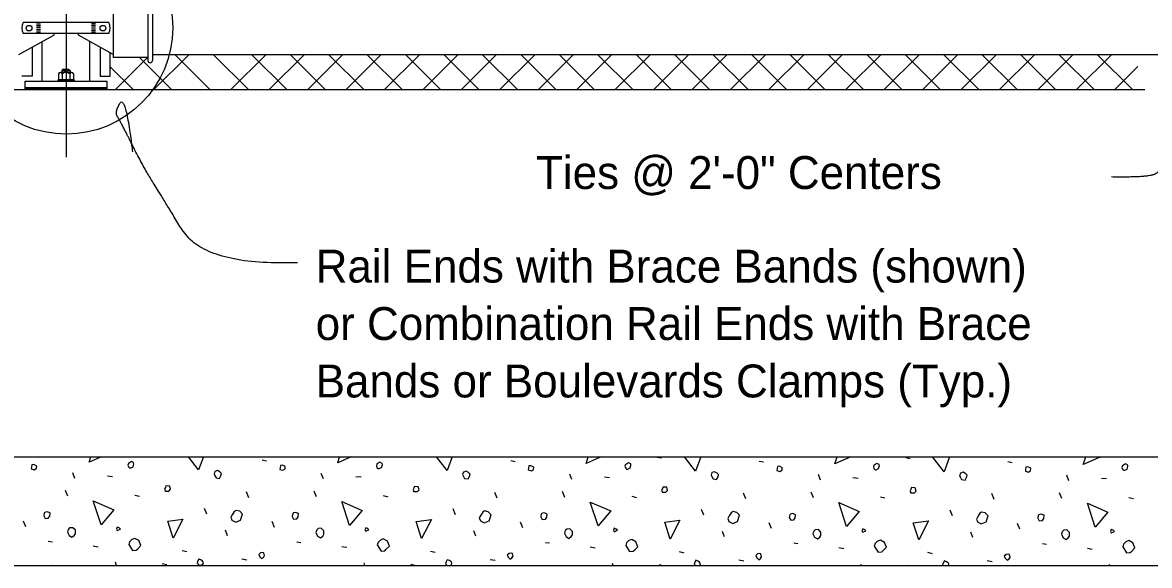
# Model space of a CAD drawing. Extents: x 0 to 41.1, y 0 to 25.9.
# Drawn here: x 11.81 to 18.72, y 14.04 to 17.37 of the extents above; entities that cross this region are included whole.
import ezdxf

# ---------------------------------------------------------------- set-up
doc = ezdxf.new("R2010")
doc.units = 0
for name, color, linetype in [('CL_Major', 7, 'Continuous'), ('Dimension', 7, 'Continuous'), ('Miscellaneous', 7, 'Continuous'), ('SteelMisc', 7, 'Continuous'), ('SupstrConc', 7, 'Continuous'), ('TextStructures', 7, 'Continuous')]:
    doc.layers.add(name, color=color, linetype=linetype)

msp = doc.modelspace()

# ---------------------------------------------------------------- linework, layer by layer
at = {"layer": 'CL_Major'}
msp.add_line((12.075, 24.4537), (12.075, 16.5436), dxfattribs=at)
at = {"layer": 'Dimension'}
msp.add_line((12.075, 17.0171), (12.075, 17.0164), dxfattribs=at)
msp.add_circle((12.0765, 17.337), 0.6527, dxfattribs=at)
for points in [[(18.4847, 16.4238), (18.7076, 16.4203), (18.7925, 16.4592), (18.9233, 16.6079), (18.8385, 16.9053), (18.796, 17.1707)], [(13.4943, 15.8955), (12.9219, 15.8776), (12.6525, 16.3184), (12.5475, 16.4863), (12.4086, 16.7637), (12.3723, 16.8197), (12.4405, 16.93), (12.4826, 16.5757)]]:
    msp.add_open_spline(points, degree=2, dxfattribs=at)
at = {"layer": 'Miscellaneous'}
for p, q in [((12.3786, 16.9573), (12.5775, 17.1562)), ((12.5254, 17.1536), (12.7217, 16.9573)), ((12.6143, 16.9573), (12.8278, 17.1708)), ((12.7439, 17.1708), (12.9574, 16.9573)), ((12.9796, 17.1708), (13.1931, 16.9573)), ((13.0857, 16.9573), (13.2992, 17.1708)), ((13.2153, 17.1708), (13.4288, 16.9573)), ((13.3214, 16.9573), (13.5349, 17.1708)), ((13.451, 17.1708), (13.6645, 16.9573)), ((13.5571, 16.9573), (13.7706, 17.1708)), ((13.6867, 17.1708), (13.9002, 16.9573)), ((13.7928, 16.9573), (14.0063, 17.1708)), ((13.9224, 17.1708), (14.1359, 16.9573)), ((14.0285, 16.9573), (14.242, 17.1708)), ((14.1581, 17.1708), (14.3716, 16.9573)), ((14.2642, 16.9573), (14.4777, 17.1708)), ((14.3938, 17.1708), (14.6073, 16.9573)), ((14.4999, 16.9573), (14.7134, 17.1708)), ((14.6295, 17.1708), (14.843, 16.9573)), ((14.7356, 16.9573), (14.9491, 17.1708)), ((14.8652, 17.1708), (15.0787, 16.9573)), ((14.9713, 16.9573), (15.1848, 17.1708)), ((15.1009, 17.1708), (15.3144, 16.9573)), ((15.207, 16.9573), (15.4205, 17.1708)), ((15.3366, 17.1708), (15.5501, 16.9573)), ((15.4427, 16.9573), (15.6562, 17.1708)), ((15.5723, 17.1708), (15.7858, 16.9573)), ((15.6784, 16.9573), (15.8919, 17.1708)), ((15.808, 17.1708), (16.0215, 16.9573)), ((15.9141, 16.9573), (16.1276, 17.1708)), ((16.0437, 17.1708), (16.2573, 16.9573)), ((16.1498, 16.9573), (16.3633, 17.1708)), ((16.2794, 17.1708), (16.493, 16.9573)), ((16.3855, 16.9573), (16.599, 17.1708)), ((16.5151, 17.1708), (16.7287, 16.9573)), ((16.6212, 16.9573), (16.8347, 17.1708)), ((16.7508, 17.1708), (16.9644, 16.9573)), ((16.8569, 16.9573), (17.0704, 17.1708)), ((16.9865, 17.1708), (17.2001, 16.9573)), ((17.0926, 16.9573), (17.3061, 17.1708)), ((17.2222, 17.1708), (17.4358, 16.9573)), ((17.3283, 16.9573), (17.5418, 17.1708)), ((17.4579, 17.1708), (17.6715, 16.9573)), ((17.564, 16.9573), (17.7776, 17.1708)), ((17.6936, 17.1708), (17.9072, 16.9573)), ((17.7997, 16.9573), (18.0133, 17.1708)), ((17.9293, 17.1708), (18.1429, 16.9573)), ((18.0354, 16.9573), (18.249, 17.1708)), ((18.165, 17.1708), (18.3786, 16.9573)), ((18.2711, 16.9573), (18.4847, 17.1708)), ((18.4007, 17.1708), (18.6143, 16.9573)), ((12.0638, 17.0788), (12.0846, 17.0788)), ((12.0638, 17.0691), (12.0846, 17.0691)), ((12.3459, 17.0974), (12.486, 16.9573)), ((18.5068, 16.9573), (18.6477, 17.0982)), ((11.825, 16.9642), (12.325, 16.9642)), ((11.825, 16.9607), (12.325, 16.9607)), ((12.6778, 14.7072), (12.6789, 14.707)), ((13.2781, 14.6876), (13.3046, 14.6823)), ((14.1839, 14.7072), (14.2027, 14.7035)), ((14.8019, 14.684), (14.8285, 14.6787)), ((15.7, 14.7053), (15.7265, 14.7)), ((16.3258, 14.6805), (16.3523, 14.6752)), ((17.2238, 14.7017), (17.2503, 14.6964)), ((17.8496, 14.677), (17.8761, 14.6717)), ((12.1291, 14.5744), (12.1167, 14.608)), ((12.3288, 14.5904), (12.3607, 14.5868)), ((13.6529, 14.5709), (13.6405, 14.6045)), ((13.8527, 14.5868), (13.8845, 14.5833)), ((15.1767, 14.5674), (15.1643, 14.601)), ((15.3765, 14.5833), (15.4083, 14.5797)), ((16.7005, 14.5638), (16.6882, 14.5974)), ((18.2243, 14.5603), (18.212, 14.5939)), ((16.9003, 14.5797), (16.9321, 14.5762)), ((18.4241, 14.5762), (18.4559, 14.5727)), ((12.0867, 14.4648), (12.0725, 14.5002)), ((12.4968, 14.4719), (12.5251, 14.4648)), ((13.195, 14.456), (13.1809, 14.4914)), ((13.6105, 14.4613), (13.5963, 14.4967)), ((14.0206, 14.4684), (14.0489, 14.4613)), ((14.7189, 14.4525), (14.7047, 14.4878)), ((15.1343, 14.4578), (15.1201, 14.4931)), ((15.5444, 14.4648), (15.5727, 14.4578)), ((16.2427, 14.4489), (16.2285, 14.4843)), ((16.6581, 14.4542), (16.644, 14.4896)), ((17.0682, 14.4613), (17.0965, 14.4542)), ((17.7665, 14.4454), (17.7523, 14.4807)), ((18.1819, 14.4507), (18.1678, 14.4861)), ((18.592, 14.4578), (18.6203, 14.4507)), ((12.9387, 14.3552), (12.9246, 14.3906)), ((14.4625, 14.3517), (14.4484, 14.3871)), ((15.9863, 14.3482), (15.9722, 14.3835)), ((17.5102, 14.3446), (17.496, 14.38)), ((11.8286, 14.2775), (11.8144, 14.3128)), ((13.3524, 14.2739), (13.3382, 14.3093)), ((14.8762, 14.2704), (14.8621, 14.3057)), ((13.0642, 14.2227), (13.0519, 14.2562)), ((14.588, 14.2191), (14.5757, 14.2527)), ((16.1119, 14.2156), (16.0995, 14.2492)), ((16.4, 14.2668), (16.3859, 14.3022)), ((17.6357, 14.212), (17.6233, 14.2456)), ((17.9238, 14.2633), (17.9097, 14.2987)), ((11.9664, 14.1891), (11.9912, 14.1855)), ((13.4903, 14.1855), (13.515, 14.182)), ((15.0141, 14.182), (15.0388, 14.1785)), ((16.5379, 14.1785), (16.5626, 14.1749)), ((18.0617, 14.1749), (18.0865, 14.1714)), ((12.2422, 14.1608), (12.2723, 14.1555)), ((12.7867, 14.1325), (12.815, 14.1254)), ((13.766, 14.1572), (13.7961, 14.1519)), ((14.3105, 14.129), (14.3388, 14.1219)), ((15.2898, 14.1537), (15.3199, 14.1484)), ((15.8343, 14.1254), (15.8626, 14.1184)), ((16.8137, 14.1502), (16.8437, 14.1449)), ((17.3581, 14.1219), (17.3864, 14.1148)), ((18.3375, 14.1466), (18.3675, 14.1413)), ((12.3855, 14.0406), (12.3783, 14.06)), ((12.6647, 14.0529), (12.693, 14.0459)), ((13.1526, 14.0812), (13.1827, 14.0759)), ((13.908, 14.0406), (13.9022, 14.0565)), ((14.1885, 14.0494), (14.2168, 14.0423)), ((14.6764, 14.0777), (14.7065, 14.0724)), ((15.4305, 14.0406), (15.426, 14.0529)), ((15.7123, 14.0459), (15.7336, 14.0406)), ((16.2002, 14.0742), (16.2303, 14.0689)), ((16.953, 14.0406), (16.9498, 14.0494)), ((17.2362, 14.0423), (17.2432, 14.0406)), ((17.7241, 14.0706), (17.7541, 14.0653)), ((18.4756, 14.0406), (18.4736, 14.0459))]:
    msp.add_line(p, q, dxfattribs=at)
msp.add_lwpolyline([(11.825, 16.9677), (12.325, 16.9677), (12.325, 16.9573), (11.825, 16.9573)], close=True, dxfattribs=at)
for points in [[(11.8621, 14.6328), (11.8816, 14.6275), (11.894, 14.6363), (11.8957, 14.6487), (11.8922, 14.6522), (11.8781, 14.6593), (11.8657, 14.6575), (11.8639, 14.6452), (11.8621, 14.6328)], [(12.2175, 14.6734), (12.2279, 14.7072)], [(12.2927, 14.7072), (12.2175, 14.6734)], [(12.465, 14.6381), (12.472, 14.6381), (12.4862, 14.6452), (12.4915, 14.6611), (12.4897, 14.6699), (12.4756, 14.677), (12.4579, 14.6664), (12.4544, 14.6558), (12.4579, 14.6452), (12.465, 14.6381)], [(12.8875, 14.6257), (12.8255, 14.7072)], [(12.9179, 14.7072), (12.8875, 14.6257)], [(13.386, 14.6292), (13.4054, 14.6239), (13.4178, 14.6328), (13.4196, 14.6452), (13.416, 14.6487), (13.4019, 14.6558), (13.3895, 14.654), (13.3877, 14.6416), (13.386, 14.6292)], [(13.7413, 14.6699), (13.7528, 14.7072)], [(13.8244, 14.7072), (13.7413, 14.6699)], [(13.9888, 14.6345), (13.9958, 14.6345), (14.01, 14.6416), (14.0153, 14.6575), (14.0135, 14.6664), (13.9994, 14.6734), (13.9817, 14.6628), (13.9782, 14.6522), (13.9817, 14.6416), (13.9888, 14.6345)], [(14.4113, 14.6222), (14.3466, 14.7072)], [(14.4431, 14.7072), (14.4113, 14.6222)], [(14.9098, 14.6257), (14.9292, 14.6204), (14.9416, 14.6292), (14.9434, 14.6416), (14.9398, 14.6452), (14.9257, 14.6522), (14.9133, 14.6505), (14.9115, 14.6381), (14.9098, 14.6257)], [(15.2651, 14.6664), (15.2777, 14.7072)], [(15.3561, 14.7072), (15.2651, 14.6664)], [(15.5126, 14.631), (15.5197, 14.631), (15.5338, 14.6381), (15.5391, 14.654), (15.5373, 14.6628), (15.5232, 14.6699), (15.5055, 14.6593), (15.502, 14.6487), (15.5055, 14.6381), (15.5126, 14.631)], [(15.9351, 14.6186), (15.8677, 14.7072)], [(15.9682, 14.7072), (15.9351, 14.6186)], [(16.7889, 14.6628), (16.8026, 14.7072)], [(16.8878, 14.7072), (16.7889, 14.6628)], [(17.0364, 14.6275), (17.0435, 14.6275), (17.0576, 14.6345), (17.0629, 14.6505), (17.0612, 14.6593), (17.047, 14.6664), (17.0293, 14.6558), (17.0258, 14.6452), (17.0293, 14.6345), (17.0364, 14.6275)], [(17.4589, 14.6151), (17.3889, 14.7072)], [(17.4933, 14.7072), (17.4589, 14.6151)], [(18.3127, 14.6593), (18.3275, 14.7072)], [(18.4195, 14.7072), (18.3127, 14.6593)], [(18.5602, 14.6239), (18.5673, 14.6239), (18.5814, 14.631), (18.5867, 14.6469), (18.585, 14.6558), (18.5708, 14.6628), (18.5531, 14.6522), (18.5496, 14.6416), (18.5531, 14.631), (18.5602, 14.6239)], [(12.9864, 14.5939), (12.9953, 14.578), (13.0165, 14.5744), (13.0253, 14.5904), (13.0289, 14.6045), (13.02, 14.6133), (13.0041, 14.6222), (12.9882, 14.6169), (12.9829, 14.601), (12.9864, 14.5939)], [(14.5103, 14.5904), (14.5191, 14.5744), (14.5403, 14.5709), (14.5492, 14.5868), (14.5527, 14.601), (14.5439, 14.6098), (14.5279, 14.6186), (14.512, 14.6133), (14.5067, 14.5974), (14.5103, 14.5904)], [(16.0341, 14.5868), (16.0429, 14.5709), (16.0641, 14.5674), (16.073, 14.5833), (16.0765, 14.5974), (16.0677, 14.6063), (16.0518, 14.6151), (16.0358, 14.6098), (16.0305, 14.5939), (16.0341, 14.5868)], [(16.4336, 14.6222), (16.453, 14.6169), (16.4654, 14.6257), (16.4672, 14.6381), (16.4636, 14.6416), (16.4495, 14.6487), (16.4371, 14.6469), (16.4354, 14.6345), (16.4336, 14.6222)], [(17.5579, 14.5833), (17.5667, 14.5674), (17.5879, 14.5638), (17.5968, 14.5797), (17.6003, 14.5939), (17.5915, 14.6027), (17.5756, 14.6116), (17.5597, 14.6063), (17.5544, 14.5904), (17.5579, 14.5833)], [(17.9574, 14.6186), (17.9769, 14.6133), (17.9892, 14.6222), (17.991, 14.6345), (17.9875, 14.6381), (17.9733, 14.6452), (17.9609, 14.6434), (17.9592, 14.631), (17.9574, 14.6186)], [(12.6842, 14.4967), (12.7054, 14.4967), (12.716, 14.5073), (12.7107, 14.5267), (12.6877, 14.5285), (12.6842, 14.5179), (12.6789, 14.509), (12.6842, 14.4967), (12.6806, 14.5002)], [(14.208, 14.4931), (14.2292, 14.4931), (14.2398, 14.5037), (14.2345, 14.5232), (14.2115, 14.5249), (14.208, 14.5143), (14.2027, 14.5055), (14.208, 14.4931), (14.2044, 14.4967)], [(15.7318, 14.4896), (15.753, 14.4896), (15.7636, 14.5002), (15.7583, 14.5196), (15.7353, 14.5214), (15.7318, 14.5108), (15.7265, 14.502), (15.7318, 14.4896), (15.7283, 14.4931)], [(17.2556, 14.4861), (17.2768, 14.4861), (17.2874, 14.4967), (17.2821, 14.5161), (17.2591, 14.5179), (17.2556, 14.5073), (17.2503, 14.4984), (17.2556, 14.4861), (17.2521, 14.4896)], [(12.2899, 14.2898), (12.2422, 14.4366), (12.3677, 14.3818), (12.2899, 14.2898)], [(13.0925, 14.3181), (13.1155, 14.3057), (13.1455, 14.3181), (13.1579, 14.3552), (13.1402, 14.3729), (13.1173, 14.3782), (13.1067, 14.3711), (13.0943, 14.3517), (13.0854, 14.3358), (13.0925, 14.3181)], [(13.8138, 14.2863), (13.766, 14.433), (13.8915, 14.3782), (13.8138, 14.2863)], [(14.6163, 14.3146), (14.6393, 14.3022), (14.6694, 14.3146), (14.6817, 14.3517), (14.6641, 14.3694), (14.6411, 14.3747), (14.6305, 14.3676), (14.6181, 14.3482), (14.6093, 14.3323), (14.6163, 14.3146)], [(15.3376, 14.2828), (15.2898, 14.4295), (15.4154, 14.3747), (15.3376, 14.2828)], [(16.8614, 14.2792), (16.8137, 14.4259), (16.9392, 14.3711), (16.8614, 14.2792)], [(18.3852, 14.2757), (18.3375, 14.4224), (18.463, 14.3676), (18.3852, 14.2757)], [(11.9382, 14.3446), (11.947, 14.3287), (11.9664, 14.3305), (11.9753, 14.3429), (11.9771, 14.3623), (11.9647, 14.3676), (11.9558, 14.3694), (11.9452, 14.3658), (11.9417, 14.3623), (11.9382, 14.3446)], [(12.7319, 14.2085), (12.6983, 14.3128), (12.792, 14.3252), (12.7319, 14.2085)], [(13.462, 14.3411), (13.4708, 14.3252), (13.4903, 14.327), (13.4991, 14.3393), (13.5009, 14.3588), (13.4885, 14.3641), (13.4797, 14.3658), (13.469, 14.3623), (13.4655, 14.3588), (13.462, 14.3411)], [(14.2557, 14.205), (14.2221, 14.3093), (14.3158, 14.3216), (14.2557, 14.205)], [(14.9858, 14.3376), (14.9946, 14.3216), (15.0141, 14.3234), (15.0229, 14.3358), (15.0247, 14.3552), (15.0123, 14.3605), (15.0035, 14.3623), (14.9929, 14.3588), (14.9893, 14.3552), (14.9858, 14.3376)], [(15.7795, 14.2014), (15.7459, 14.3057), (15.8396, 14.3181), (15.7795, 14.2014)], [(16.1401, 14.311), (16.1631, 14.2987), (16.1932, 14.311), (16.2056, 14.3482), (16.1879, 14.3658), (16.1649, 14.3711), (16.1543, 14.3641), (16.1419, 14.3446), (16.1331, 14.3287), (16.1401, 14.311)], [(16.5096, 14.334), (16.5184, 14.3181), (16.5379, 14.3199), (16.5467, 14.3323), (16.5485, 14.3517), (16.5361, 14.357), (16.5273, 14.3588), (16.5167, 14.3552), (16.5131, 14.3517), (16.5096, 14.334)], [(17.3033, 14.1979), (17.2697, 14.3022), (17.3634, 14.3146), (17.3033, 14.1979)], [(17.664, 14.3075), (17.6869, 14.2951), (17.717, 14.3075), (17.7294, 14.3446), (17.7117, 14.3623), (17.6887, 14.3676), (17.6781, 14.3605), (17.6657, 14.3411), (17.6569, 14.3252), (17.664, 14.3075)], [(18.0334, 14.3305), (18.0423, 14.3146), (18.0617, 14.3163), (18.0705, 14.3287), (18.0723, 14.3482), (18.0599, 14.3535), (18.0511, 14.3552), (18.0405, 14.3517), (18.037, 14.3482), (18.0334, 14.3305)], [(12.0831, 14.2456), (12.0937, 14.2244), (12.1114, 14.2138), (12.1255, 14.2244), (12.1326, 14.235), (12.1326, 14.2562), (12.1167, 14.2722), (12.0973, 14.2704), (12.0884, 14.2615), (12.0831, 14.2456)], [(12.3889, 14.2545), (12.4084, 14.2633), (12.4013, 14.2704), (12.3889, 14.2757), (12.3836, 14.2633), (12.3889, 14.2545)], [(13.6069, 14.2421), (13.6175, 14.2209), (13.6352, 14.2103), (13.6494, 14.2209), (13.6564, 14.2315), (13.6564, 14.2527), (13.6405, 14.2686), (13.6211, 14.2668), (13.6122, 14.258), (13.6069, 14.2421)], [(13.9128, 14.2509), (13.9322, 14.2598), (13.9251, 14.2668), (13.9128, 14.2722), (13.9075, 14.2598), (13.9128, 14.2509)], [(15.1308, 14.2386), (15.1414, 14.2174), (15.159, 14.2067), (15.1732, 14.2174), (15.1802, 14.228), (15.1802, 14.2492), (15.1643, 14.2651), (15.1449, 14.2633), (15.1361, 14.2545), (15.1308, 14.2386)], [(15.4366, 14.2474), (15.456, 14.2562), (15.4489, 14.2633), (15.4366, 14.2686), (15.4313, 14.2562), (15.4366, 14.2474)], [(16.6546, 14.235), (16.6652, 14.2138), (16.6828, 14.2032), (16.697, 14.2138), (16.7041, 14.2244), (16.7041, 14.2456), (16.6882, 14.2615), (16.6687, 14.2598), (16.6599, 14.2509), (16.6546, 14.235)], [(16.9604, 14.2439), (16.9798, 14.2527), (16.9728, 14.2598), (16.9604, 14.2651), (16.9551, 14.2527), (16.9604, 14.2439)], [(18.1784, 14.2315), (18.189, 14.2103), (18.2067, 14.1997), (18.2208, 14.2103), (18.2279, 14.2209), (18.2279, 14.2421), (18.212, 14.258), (18.1925, 14.2562), (18.1837, 14.2474), (18.1784, 14.2315)], [(18.4842, 14.2403), (18.5036, 14.2492), (18.4966, 14.2562), (18.4842, 14.2615), (18.4789, 14.2492), (18.4842, 14.2403)], [(12.4597, 14.1696), (12.4826, 14.1325), (12.5056, 14.1343), (12.5145, 14.1431), (12.5339, 14.1626), (12.5215, 14.1926), (12.4968, 14.2067), (12.4791, 14.1997), (12.465, 14.1855), (12.4597, 14.1696)], [(13.9835, 14.1661), (14.0065, 14.129), (14.0294, 14.1307), (14.0383, 14.1396), (14.0577, 14.159), (14.0453, 14.1891), (14.0206, 14.2032), (14.0029, 14.1961), (13.9888, 14.182), (13.9835, 14.1661)], [(15.5073, 14.1626), (15.5303, 14.1254), (15.5532, 14.1272), (15.5621, 14.136), (15.5815, 14.1555), (15.5692, 14.1855), (15.5444, 14.1997), (15.5267, 14.1926), (15.5126, 14.1785), (15.5073, 14.1626)], [(17.0311, 14.159), (17.0541, 14.1219), (17.0771, 14.1237), (17.0859, 14.1325), (17.1053, 14.1519), (17.093, 14.182), (17.0682, 14.1961), (17.0505, 14.1891), (17.0364, 14.1749), (17.0311, 14.159)], [(18.5549, 14.1555), (18.5779, 14.1184), (18.6009, 14.1201), (18.6097, 14.129), (18.6292, 14.1484), (18.6168, 14.1785), (18.592, 14.1926), (18.5744, 14.1855), (18.5602, 14.1714), (18.5549, 14.1555)], [(13.264, 14.0936), (13.2746, 14.083), (13.2852, 14.0901), (13.2923, 14.1007), (13.2887, 14.1184), (13.2799, 14.1201), (13.2675, 14.1184), (13.2569, 14.1077), (13.264, 14.0936)], [(14.7878, 14.0901), (14.7984, 14.0795), (14.809, 14.0865), (14.8161, 14.0971), (14.8126, 14.1148), (14.8037, 14.1166), (14.7913, 14.1148), (14.7807, 14.1042), (14.7878, 14.0901)], [(16.3116, 14.0865), (16.3222, 14.0759), (16.3328, 14.083), (16.3399, 14.0936), (16.3364, 14.1113), (16.3275, 14.1131), (16.3152, 14.1113), (16.3045, 14.1007), (16.3116, 14.0865)], [(17.8354, 14.083), (17.846, 14.0724), (17.8566, 14.0795), (17.8637, 14.0901), (17.8602, 14.1077), (17.8513, 14.1095), (17.839, 14.1077), (17.8284, 14.0971), (17.8354, 14.083)], [(11.9943, 14.0406), (11.993, 14.0423), (12.1927, 14.0406)], [(12.8892, 14.0441), (12.9016, 14.0423), (12.914, 14.0476), (12.9175, 14.0583), (12.9122, 14.0671), (12.9016, 14.0742), (12.8892, 14.0795), (12.8822, 14.0653), (12.8786, 14.0547), (12.8892, 14.0441)], [(14.4295, 14.0406), (14.4378, 14.0441), (14.4413, 14.0547), (14.436, 14.0636), (14.4254, 14.0706), (14.413, 14.0759), (14.406, 14.0618), (14.4024, 14.0512), (14.413, 14.0406)], [(15.9616, 14.0406), (15.9651, 14.0512), (15.9598, 14.06), (15.9492, 14.0671), (15.9369, 14.0724), (15.9298, 14.0583), (15.9262, 14.0476), (15.9333, 14.0406)], [(17.4866, 14.0406), (17.489, 14.0476), (17.4836, 14.0565), (17.473, 14.0636), (17.4607, 14.0689), (17.4536, 14.0547), (17.4501, 14.0441), (17.4536, 14.0406)]]:
    msp.add_lwpolyline(points, dxfattribs=at)
at = {"layer": 'SteelMisc'}
for p, q in [((12.3646, 17.4258), (12.3646, 17.1536)), ((12.5775, 17.4454), (12.5775, 17.1357)), ((12.6044, 17.4454), (12.6044, 17.1357)), ((12.3374, 17.3685), (11.8126, 17.3685)), ((11.895, 17.3607), (11.9185, 17.3607)), ((11.895, 17.3511), (11.9185, 17.3511)), ((12.255, 17.3607), (12.2316, 17.3607)), ((12.255, 17.3511), (12.2316, 17.3511)), ((11.7855, 17.1717), (11.9994, 17.2902)), ((12.3374, 17.3007), (11.8126, 17.3007)), ((11.895, 17.3402), (11.9185, 17.3402)), ((11.895, 17.3285), (11.9185, 17.3285)), ((11.895, 17.3167), (11.9185, 17.3167)), ((11.895, 17.3069), (11.9185, 17.3069)), ((12.3646, 17.1717), (12.1506, 17.2902)), ((12.255, 17.3402), (12.2316, 17.3402)), ((12.255, 17.3285), (12.2316, 17.3285)), ((12.255, 17.3167), (12.2316, 17.3167)), ((12.255, 17.3069), (12.2316, 17.3069)), ((11.8667, 17.2167), (11.8667, 17.0406)), ((11.9292, 17.0093), (11.9292, 17.2513)), ((12.2209, 17.0093), (12.2209, 17.2513)), ((12.2834, 17.2167), (12.2834, 17.0406)), ((12.3459, 17.0406), (12.3459, 17.182)), ((12.5775, 17.1536), (12.3646, 17.1536)), ((21.5457, 17.1708), (12.6044, 17.1708)), ((12.0589, 17.0837), (12.0492, 17.074)), ((12.0492, 17.074), (12.0492, 17.0627)), ((12.0492, 17.074), (12.1007, 17.074)), ((12.0589, 17.0837), (12.0894, 17.0837)), ((12.0894, 17.0837), (12.1007, 17.074)), ((12.1007, 17.074), (12.1007, 17.0627)), ((11.8667, 17.0406), (11.8042, 17.0406)), ((12.0253, 17.0164), (12.0253, 17.0093)), ((12.0253, 17.0164), (12.1247, 17.0164)), ((12.0296, 17.054), (12.0296, 17.0164)), ((12.1204, 17.0164), (12.0296, 17.0164)), ((12.1091, 17.0627), (12.0409, 17.0627)), ((12.0523, 17.0543), (12.0523, 17.0164)), ((12.0977, 17.0543), (12.0977, 17.0164)), ((12.1204, 17.054), (12.1204, 17.0164)), ((12.1247, 17.0164), (12.1247, 17.0093)), ((12.2834, 17.0406), (12.3459, 17.0406)), ((11.9552, 16.9677), (12.1948, 16.9677))]:
    msp.add_line(p, q, dxfattribs=at)
msp.add_lwpolyline([(11.825, 17.0093), (12.325, 17.0093), (12.325, 16.9677), (11.825, 16.9677)], close=True, dxfattribs=at)
for centre, radius, start, end in [((12.5909, 17.1355), 0.0134, 180, 0), ((12.041, 17.0509), 0.0118, 16.59863, 164.70054), ((12.075, 17.028), 0.0347, 49.20147, 130.79853), ((12.109, 17.051), 0.0118, 15.15064, 163.50417)]:
    msp.add_arc(centre, radius, start, end, dxfattribs=at)
for centre, major_axis, start_param, end_param in [((11.8818, 17.3345), (-0.0776, 0), 5.810211, 6.75616), ((12.2683, 17.3345), (0.0776, 0), 5.810211, 6.75616), ((11.8618, 17.3365), (0.146, 0), 5.947976, 6.024627), ((12.2882, 17.3365), (-0.146, 0), 0.258558, 0.335209)]:
    msp.add_ellipse(centre, major_axis=major_axis, ratio=0.957868, start_param=start_param, end_param=end_param, dxfattribs=at)
for centre, major_axis in [((11.8485, 17.334), (0.0178, 0)), ((12.3016, 17.334), (-0.0178, 0))]:
    msp.add_ellipse(centre, major_axis=major_axis, ratio=0.957868, dxfattribs=at)
at = {"layer": 'SupstrConc'}
for p, q in [((5.5315, 16.9573), (18.6893, 16.9573)), ((0.6881, 14.7072), (23.462, 14.7072)), ((0.6881, 14.0406), (23.462, 14.0406))]:
    msp.add_line(p, q, dxfattribs=at)

# ---------------------------------------------------------------- texts
at = {"layer": 'Dimension'}
for s, p in [('Rail Ends with Brace Bands (shown)', (13.6059, 15.7745)), ('or Combination Rail Ends with Brace', (13.6059, 15.4225)), ('Bands or Boulevards Clamps (Typ.)', (13.6059, 15.0705))]:
    msp.add_text(s, height=0.2016, dxfattribs=at).set_placement(p)
at = {"layer": 'TextStructures'}
msp.add_text('Ties @ 2\'-0" Centers', height=0.2016, dxfattribs=at).set_placement((14.9569, 16.3481))

doc.saveas('drawing.dxf')
